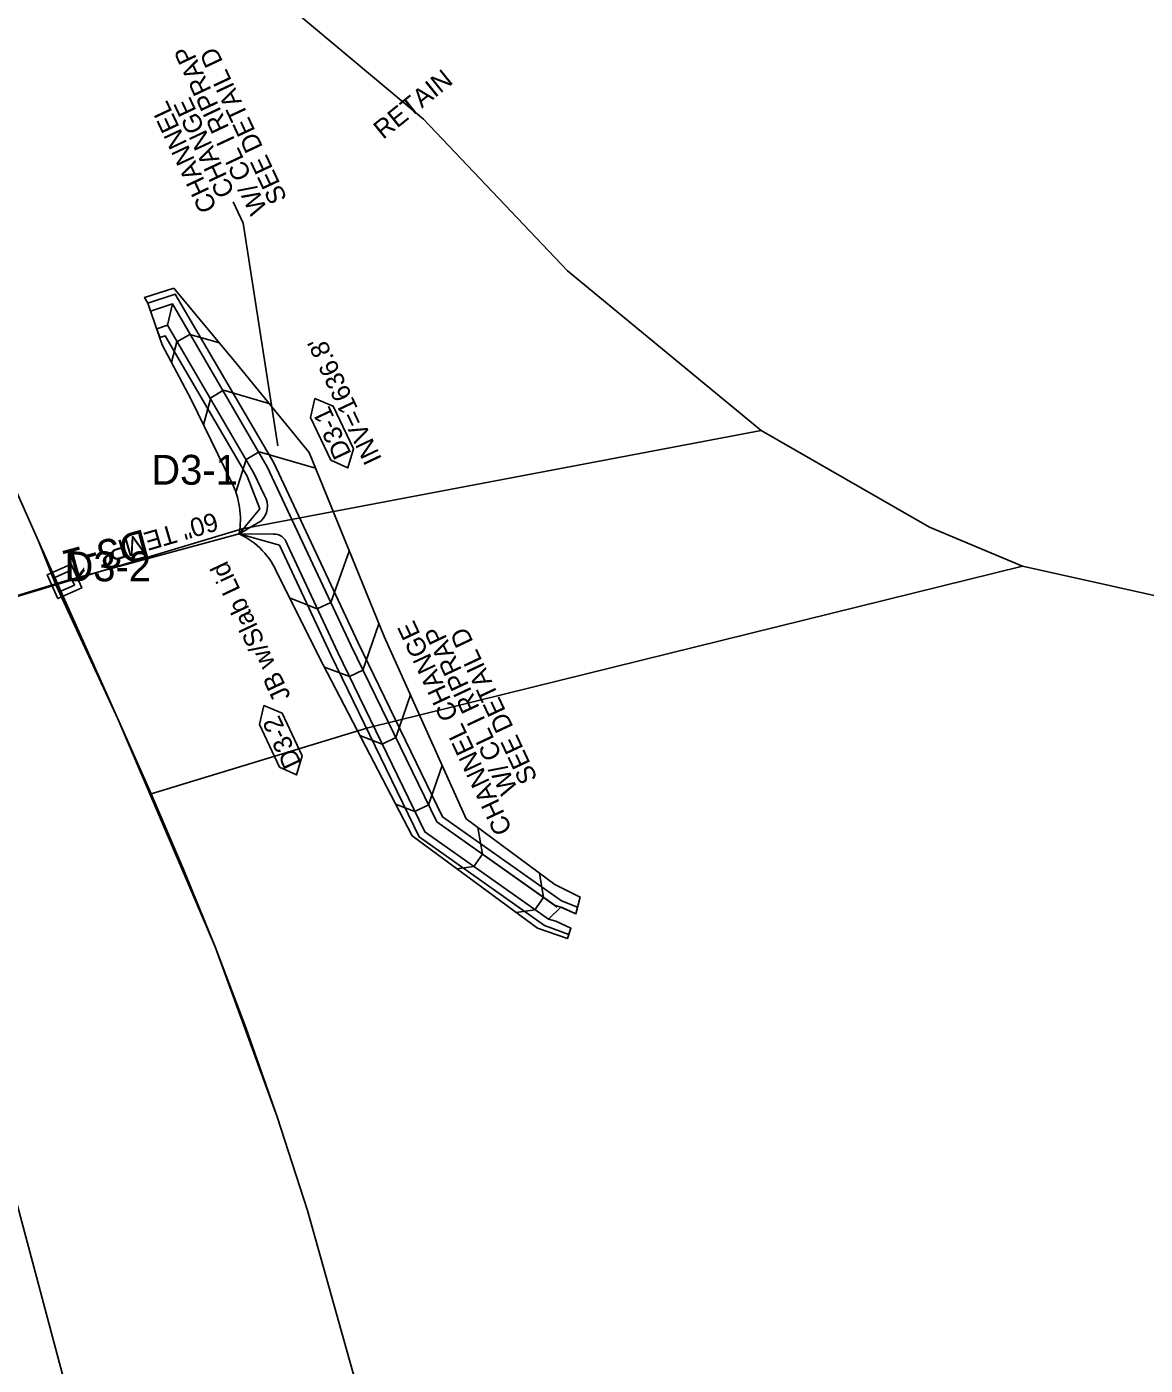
# Model space of a CAD drawing. Extents: x 465700 to 483515, y 488970 to 507540.
# Drawn here: x 477838.2 to 478138.3, y 499135.1 to 499494.2 of the extents above; entities that cross this region are included whole.
import ezdxf

# ---------------------------------------------------------------- set-up
doc = ezdxf.new("R2010")
doc.units = 0
for name, color, linetype in [('Exist Plan Preparation Watershed Blue', 7, 'Continuous'), ('Prop Drainage Structure Box Number Symbol CELL', 7, 'Continuous'), ('Prop Drainage Structure Junction Box with Slab Lid Label', 7, 'Continuous'), ('Prop Drainage Structure Junction Box with Slab Lid TB 840 34 CELL', 7, 'Continuous'), ('Prop Drainage Structure Pipe Collar Label', 7, 'Continuous'), ('Prop Drainage Structure Pipe RCP 60in Class III', 7, 'Continuous'), ('Prop Drainage Structure Pipe RCP 60in Class III Label', 7, 'Continuous'), ('Prop Drainage Structure Pipe Stub Out CELL', 7, 'Continuous'), ('Prop Drainage Structure Plot Symbol 20 Scale', 7, 'Continuous'), ('Prop Drainage Structure Plot Symbol 50 Scale', 7, 'Continuous'), ('Prop Drainage Structure Tops and Inverts LABEL', 7, 'Continuous'), ('Prop Earthen Structure Head Ditch', 7, 'Continuous'), ('Prop Erosion Rip Rap Class II', 7, 'Continuous'), ('Prop Erosion Rip Rap Pad at Outlet Label', 7, 'Continuous'), ('Scratch_Level_4', 7, 'Continuous'), ('Scratch_Level_8', 7, 'Continuous')]:
    doc.layers.add(name, color=color, linetype=linetype)

msp = doc.modelspace()

# ---------------------------------------------------------------- linework, layer by layer
at = {"layer": 'Exist Plan Preparation Watershed Blue'}
for points in [[(477618.98, 499766.16), (477648.78, 499729.18), (477683.33, 499680.45), (477711.15, 499635.72), (477736.76, 499588.43), (477746.56, 499568.42), (477759.49, 499540.06), (477764.82, 499528.09), (477773.77, 499507.99), (477803.41, 499441.41), (477841.35, 499356.21), (477862.6, 499308.49), (477888.75, 499247.35), (477905.42, 499201.8), (477913.55, 499176.64), (477929.73, 499118.92)], [(478176.46, 499333.67), (478105.39, 499349.47), (478080.37, 499359.96), (478035.25, 499385.83), (477983.32, 499428.7), (477944.68, 499469.38), (477867.06, 499534.37), (477836.92, 499549.34), (477795.57, 499562.48), (477744.68, 499572.28), (477767.35, 499587.11), (477736.76, 499588.43), (477711.15, 499635.72), (477697.3, 499658.65), (477683.33, 499680.45), (477666.94, 499704.35), (477653.6, 499722.79), (477636.96, 499744.16)], [(477858.24, 499093.41), (477832.51, 499190.03), (477802.27, 499285.34), (477767.58, 499379.12), (477747.49, 499427.65), (477728.52, 499471.17), (477710.77, 499509.04), (477685.16, 499561.27), (477643.08, 499639.33), (477611.01, 499694.79), (477581.24, 499742.27)], [(478176.46, 499333.67), (478105.39, 499349.47), (478080.37, 499359.96), (478035.25, 499385.83), (477983.32, 499428.7), (477944.68, 499469.38), (477867.06, 499534.37)], [(477773.77, 499507.99), (477803.41, 499441.41), (477841.35, 499356.21), (477853.65, 499328.59), (477862.6, 499308.49), (477871.55, 499288.39), (477880.37, 499267.97), (477888.75, 499247.35), (477897.09, 499225.48), (477905.42, 499201.8), (477913.55, 499176.64), (477929.73, 499118.92)]]:
    msp.add_lwpolyline(points, dxfattribs=at)
at = {"layer": 'Prop Drainage Structure Box Number Symbol CELL'}
for points in [[(477919.75, 499377.94), (477914.36, 499389.34), (477915.53, 499394.43), (477920.45, 499392.39), (477925.84, 499381), (477924.31, 499375.85), (477919.75, 499377.94)], [(477906.01, 499295.59), (477900.62, 499306.99), (477901.79, 499312.08), (477906.71, 499310.04), (477912.1, 499298.64), (477910.57, 499293.5), (477906.01, 499295.59)]]:
    msp.add_lwpolyline(points, dxfattribs=at)
at = {"layer": 'Prop Drainage Structure Junction Box with Slab Lid TB 840 34 CELL'}
for p, q in [((477846.52, 499344.6), (477846.52, 499344.6)), ((477847.53, 499347.24), (477847.53, 499347.24)), ((477848.35, 499345.42), (477848.35, 499345.42)), ((477850.17, 499346.23), (477850.17, 499346.23)), ((477849.16, 499343.59), (477849.16, 499343.59))]:
    msp.add_line(p, q, dxfattribs=at)
msp.add_lwpolyline([(477849.36, 499348.06), (477850.99, 499344.4), (477847.33, 499342.78), (477845.71, 499346.43)], close=True, dxfattribs=at)
at = {"layer": 'Prop Drainage Structure Pipe RCP 60in Class III'}
msp.add_line((477895.17, 499358.11), (477848.35, 499345.42), dxfattribs=at)
at = {"layer": 'Prop Drainage Structure Pipe RCP 60in Class III Label'}
for p, q in [((477877.27, 499419.83), (477871.39, 499417.89)), ((477875.97, 499414.13), (477873.09, 499413.16))]:
    msp.add_line(p, q, dxfattribs=at)
at = {"layer": 'Prop Drainage Structure Pipe Stub Out CELL'}
msp.add_line((477895.17, 499358.11), (477895.17, 499358.11), dxfattribs=at)
msp.add_line((477895.17, 499358.11), (477895.17, 499358.11), dxfattribs=at)
msp.add_lwpolyline([(477895.15, 499358.1), (477895.16, 499358.12), (477895.18, 499358.11), (477895.17, 499358.09), (477895.15, 499358.1)], dxfattribs=at)
at = {"layer": 'Prop Drainage Structure Plot Symbol 20 Scale'}
msp.add_lwpolyline([(477849.36, 499348.06), (477850.99, 499344.4), (477847.33, 499342.78), (477845.71, 499346.43)], close=True, dxfattribs=at)
at = {"layer": 'Prop Drainage Structure Plot Symbol 50 Scale'}
msp.add_lwpolyline([(477850.12, 499350.04), (477852.97, 499343.64), (477846.57, 499340.79), (477843.72, 499347.19)], close=True, dxfattribs=at)
at = {"layer": 'Prop Earthen Structure Head Ditch'}
for p, q in [((477870.67, 499420.04), (477878.06, 499422.46)), ((477875.97, 499414.13), (477877.27, 499419.83)), ((477877.27, 499419.83), (477902.73, 499376.17)), ((477877.27, 499419.83), (477902.73, 499376.17)), ((477875.3, 499411.31), (477873.89, 499410.83)), ((477893.08, 499372.18), (477882.33, 499394.2)), ((477893.08, 499372.18), (477893.08, 499372.18)), ((477895.17, 499358.11), (477900.97, 499361.57)), ((477895.17, 499358.11), (477904.35, 499358.1)), ((477916.56, 499325.29), (477905.54, 499347.29)), ((477941.6, 499277.1), (477916.56, 499325.29)), ((477981.69, 499259.66), (477986, 499257.98)), ((477978.23, 499254.76), (477981.54, 499258.02)), ((477977.08, 499253.13), (477983.63, 499250.7))]:
    msp.add_line(p, q, dxfattribs=at)
for points in [[(477882.33, 499394.2), (477874.58, 499408.85), (477870.67, 499420.04), (477869.78, 499421.51), (477877.67, 499424.06)], [(477956.09, 499281.7), (477934.08, 499330.6), (477913.94, 499379.96), (477894.36, 499403.97), (477877.67, 499424.06)], [(477875.97, 499414.13), (477899.11, 499374.47)], [(477875.97, 499414.13), (477899.11, 499374.47)], [(477877.03, 499404.21), (477878.46, 499409.64), (477881.94, 499411.67), (477889.88, 499409.36)], [(477885.65, 499387.4), (477887.56, 499394.66), (477891.03, 499396.69), (477903.18, 499393.16)], [(477894.31, 499369.29), (477897.09, 499378.1), (477900.57, 499380.13), (477915.66, 499375.73)], [(477901.95, 499368.41), (477899.11, 499374.47)], [(477980.54, 499258.03), (477948.19, 499280.86), (477925.29, 499328.07), (477902.73, 499376.17)], [(477908.74, 499363.35), (477902.73, 499376.17)], [(477979.95, 499258.44), (477948.19, 499280.86), (477925.29, 499328.07), (477908.74, 499363.35)], [(477978.23, 499254.76), (477945.04, 499278.19), (477921.68, 499326.35), (477908.05, 499355.41)], [(477924.75, 499353.46), (477919.8, 499339.77), (477916.16, 499338.06), (477908.7, 499340.98)], [(477932.7, 499333.97), (477928.42, 499321.62), (477924.8, 499319.86), (477918.06, 499322.39)], [(477941.14, 499314.92), (477937.19, 499303.53), (477933.57, 499301.77), (477927.61, 499304.02)], [(477949.64, 499296.04), (477945.97, 499285.45), (477942.34, 499283.69), (477937.16, 499285.64)], [(477956.09, 499281.7), (477979.91, 499264.05), (477986.71, 499260.72), (477985.56, 499256.25), (477981.88, 499257.89), (477979.97, 499258.43)], [(477941.6, 499277.1), (477975.24, 499252.36), (477983.25, 499249.59), (477984.21, 499252.36), (477980.18, 499254.28), (477978.23, 499254.76)], [(477959.21, 499279.39), (477960.45, 499272.21), (477958.13, 499268.92), (477953.61, 499268.26)], [(477975.75, 499267.13), (477976.87, 499260.62), (477974.55, 499257.33), (477969.49, 499256.59)]]:
    msp.add_lwpolyline(points, dxfattribs=at)
for centre, radius, start, end in [((477873.68, 499362.11), 21.86, 349.4561, 27.4367), ((477897.55, 499365.55), 5.25, 310.672, 32.9929), ((477887.02, 499339.92), 19.93, 21.703, 65.885), ((477904.52, 499354.44), 3.66, 15.3464, 92.6245)]:
    msp.add_arc(centre, radius, start, end, dxfattribs=at)
at = {"layer": 'Prop Erosion Rip Rap Class II'}
msp.add_lwpolyline([(477981.54, 499258.02), (477985.56, 499256.25), (477986, 499257.98), (477981.69, 499259.66), (477949.76, 499282.2), (477927.09, 499328.93), (477904.46, 499377.18), (477878.06, 499422.46), (477870.67, 499420.04), (477871.39, 499417.89), (477877.27, 499419.83), (477875.97, 499414.13), (477873.09, 499413.16), (477873.89, 499410.83), (477875.3, 499411.31), (477897.3, 499373.62), (477900.77, 499364.85), (477895.17, 499358.11), (477895.17, 499358.11), (477905.98, 499355.15), (477919.87, 499325.49), (477943.47, 499276.85), (477977.08, 499253.13), (477983.63, 499250.7), (477984.21, 499252.36), (477980.18, 499254.28), (477978.23, 499254.76), (477981.54, 499258.02)], dxfattribs=at)
at = {"layer": 'Prop Erosion Rip Rap Pad at Outlet Label'}
msp.add_lwpolyline([(477905.58, 499381.79), (477896.28, 499441.45), (477893.56, 499447.2)], dxfattribs=at)
at = {"layer": 'Scratch_Level_4'}
for points in [[(477846, 499344.45), (477895.99, 499359.48), (478035.25, 499385.83), (477983.32, 499428.7), (477944.68, 499469.38), (477867.06, 499534.37), (477836.92, 499549.34), (477795.57, 499562.48), (477744.68, 499572.28), (477764.82, 499528.09), (477803.41, 499441.41), (477841.35, 499356.21)], [(477846, 499344.45), (477862.6, 499308.49), (477871.55, 499288.39), (477929.76, 499306.12), (478105.39, 499349.47), (478080.37, 499359.96), (478035.25, 499385.83), (477983.32, 499428.7), (477944.68, 499469.38), (477867.06, 499534.37), (477836.92, 499549.34), (477795.57, 499562.48), (477744.68, 499572.28), (477764.82, 499528.09), (477803.41, 499441.41), (477841.35, 499356.21)]]:
    msp.add_lwpolyline(points, close=True, dxfattribs=at)
msp.add_lwpolyline([(477740.91, 499312.84), (477846, 499344.45), (477896, 499359.49)], dxfattribs=at)
at = {"layer": 'Scratch_Level_8'}
for p, q in [((477895.17, 499358.11), (477848.35, 499345.42)), ((477848.35, 499345.42), (477740.9, 499312.87))]:
    msp.add_line(p, q, dxfattribs=at)

# ---------------------------------------------------------------- texts
at = {"layer": 'Prop Drainage Structure Box Number Symbol CELL'}
for s, p in [('D3-1', (477925.44, 499379.68)), ('D3-2', (477912.01, 499296.67))]:
    msp.add_text(s, height=5, rotation=115.2909, dxfattribs=at).set_placement(p)
at = {"layer": 'Prop Drainage Structure Junction Box with Slab Lid Label'}
msp.add_text('JB w/Slab Lid', height=5, rotation=115.2938, dxfattribs=at).set_placement((477909.13, 499314.58))
at = {"layer": 'Prop Drainage Structure Pipe Collar Label'}
msp.add_text('RETAIN', height=5, rotation=38.9009, dxfattribs=at).set_placement((477933.82, 499463.8))
at = {"layer": 'Prop Drainage Structure Pipe RCP 60in Class III Label'}
msp.add_text('60" TEMP', height=5, rotation=196.3177, dxfattribs=at).set_placement((477888.65, 499364.02))
at = {"layer": 'Prop Drainage Structure Pipe Stub Out CELL'}
msp.add_text('SO', height=0.0104, rotation=19.0017, dxfattribs=at).set_placement((477895.16, 499358.1))
at = {"layer": 'Prop Drainage Structure Tops and Inverts LABEL'}
msp.add_text("INV=1636.8'", height=5, rotation=115.2938, dxfattribs=at).set_placement((477933.58, 499378.22))
at = {"layer": 'Prop Erosion Rip Rap Pad at Outlet Label'}
for s, p in [('W/ CL I RIPRAP', (477902.87, 499445.26)), ('SEE DETAIL D', (477908.16, 499448.12)), ('CHANNEL ', (477889.39, 499445.73)), ('CHANGE', (477894.11, 499449.79)), ('CHANNEL CHANGE', (477968.55, 499278.77)), ('W/ CL I RIPRAP', (477970.06, 499289.66)), ('SEE DETAIL D', (477975.34, 499292.52))]:
    msp.add_text(s, height=5, rotation=115.1706, dxfattribs=at).set_placement(p)
at = {"layer": 'Scratch_Level_8'}
for s, p in [('D3-1', (477871.64, 499371.34)), ('D3-2', (477848.35, 499345.42))]:
    msp.add_text(s, height=8, dxfattribs=at).set_placement(p)
msp.add_text('D3-1', height=8, rotation=195.1683, dxfattribs=at).set_placement((477869.66, 499359.48))

doc.saveas('drawing.dxf')
